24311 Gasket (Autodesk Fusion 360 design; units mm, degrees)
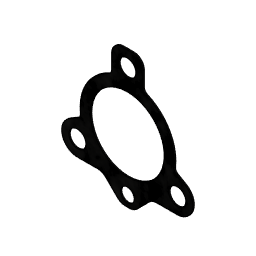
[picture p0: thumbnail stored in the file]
parameter "Bolt_Hole_Tolerance" = 0.7937 (= "( 1 / 32 ) * 1 in")
parameter "Bell_Tolerance" = 0.1984 (= "( 1 / 128 ) * 1 in")
parameter "Orifice_Hole_Tolerance" = 0.1984 (= "( 1 / 128 ) * 1 in")
parameter "d6" = 11.1125 (= "( 7 / 16 ) * 1 in")
sketch "Main Profile" plane through (0, 0, 0) normal (0, 1, 0) x axis (1, 0, 0)
  line L1 (0, -34.925) -> (0, 0)
  line L2 (0, -44.45) -> (0, -34.925)
  line L3 (3.175, -44.45) -> (-3.175, -44.45)
  line L4 (30.2459, 17.4625) -> (0, 0)
  line L5 (-30.2459, 17.4625) -> (0, 0)
  line L6 (9.525, -29.0994) -> (9.525, -38.1)
  line L7 (30.2459, 26.9875) -> (15.0812, 26.9875)
  line L8 (29.9633, 6.3008) -> (35.0084, 9.2136)
  line L9 (0, 31.75) -> (0, 0)
  line L10 (0, 38.1) -> (0, 31.75)
  line L11 (3.9688, 38.1) -> (-3.9688, 38.1)
  line L12 (15.0812, 26.9875) -> (3.9688, 38.1)
  line L13 (-15.0812, 26.9875) -> (-3.9688, 38.1)
  line L14 (-30.2459, 26.9875) -> (-15.0812, 26.9875)
  line L15 (-29.9633, 6.3008) -> (-35.0084, 9.2136)
  line L16 (-9.525, -29.0994) -> (-9.525, -38.1)
  circle C1 centre (0, 0) radius 22.3242
  circle C2 centre (0, -34.925) radius 5.1594
  circle C3 centre (30.2459, 17.4625) radius 5.1594
  circle C4 centre (-30.2459, 17.4625) radius 5.1594
  arc A1 centre (3.175, -38.1) radius 6.35 clockwise from (9.525, -38.1) to (3.175, -44.45)
  arc A2 centre (12.7, -29.0994) radius 3.175 clockwise from (9.525, -29.0994) to (11.43, -26.1894)
  arc A3 centre (0, 0) radius 28.575 clockwise from (28.3957, 3.196) to (11.43, -26.1894)
  arc A4 centre (30.2459, 17.4625) radius 9.525 clockwise from (30.2459, 26.9875) to (35.0084, 9.2136)
  arc A5 centre (31.5508, 3.5512) radius 3.175 clockwise from (28.3957, 3.196) to (29.9633, 6.3008)
  circle C5 centre (0, 31.75) radius 3.9688
  arc A6 centre (-30.2459, 17.4625) radius 9.525 clockwise from (-35.0084, 9.2136) to (-30.2459, 26.9875)
  arc A7 centre (-31.5508, 3.5512) radius 3.175 clockwise from (-29.9633, 6.3008) to (-28.3957, 3.196)
  arc A8 centre (0, 0) radius 28.575 clockwise from (-11.43, -26.1894) to (-28.3957, 3.196)
  arc A9 centre (-12.7, -29.0994) radius 3.175 clockwise from (-11.43, -26.1894) to (-9.525, -29.0994)
  arc A10 centre (-3.175, -38.1) radius 6.35 clockwise from (-3.175, -44.45) to (-9.525, -38.1)
  point P1 (0, 0)
  point P2 (0, 0)
  point P3 (0, 0)
  point P4 (0, -34.925)
  point P5 (0, -34.925)
  point P6 (0, -34.925)
  point P10 (0, -44.45)
  point P7 (0, -44.45)
  point P30 (0, 31.75)
  point P31 (0, 31.75)
  point P32 (0, 31.75)
  point P36 (0, 38.1)
  point P33 (0, 38.1)
  point P9 (3.175, -44.45)
  point P51 (-3.175, -44.45)
  point P17 (9.525, -38.1)
  point P49 (-9.525, -38.1)
  point P19 (9.525, -29.0994)
  point P48 (-9.525, -29.0994)
  point P20 (11.43, -26.1894)
  point P46 (-11.43, -26.1894)
  point P22 (28.3957, 3.196)
  point P44 (-28.3957, 3.196)
  point P24 (15.0812, 26.9875)
  point P38 (-15.0812, 26.9875)
  point P25 (30.2459, 26.9875)
  point P39 (-30.2459, 26.9875)
  point P26 (35.0084, 9.2136)
  point P41 (-35.0084, 9.2136)
  point P28 (29.9633, 6.3008)
  point P42 (-29.9633, 6.3008)
  point P35 (3.9688, 38.1)
  point P37 (-3.9688, 38.1)
  point P14 (0, 0)
  point P34 (-3.9688, 38.1)
  point P23 (0, 0)
  point P11 (0, 0)
  coincident P1 P2
  coincident P1 P3
  vertical L1
  coincident P4 P5
  coincident P5 P6
  vertical L2
  horizontal L3
  midpoint L3 P10
  coincident P7 P10
  tangent L3 A1
  vertical L6
  tangent A1 L6
  tangent L6 A2
  tangent A2 A3
  concentric C1 A3
  horizontal L7
  tangent L7 A4
  concentric C3 A4
  tangent A4 L8
  tangent L8 A5
  tangent A3 A5
  parallel L1 L9
  coincident P30 P31
  coincident P31 P32
  parallel L9 L10
  horizontal L11
  midpoint L11 P36
  coincident P33 P36
  symmetric L1 P9 P51
  symmetric L1 P17 P49
  symmetric L1 A1 A10
  symmetric L1 P19 P48
  symmetric L1 P20 P46
  symmetric L1 A2 A9
  symmetric L1 P22 P44
  symmetric L1 A3 A8
  symmetric L1 P24 P38
  symmetric L1 P25 P39
  symmetric L1 P26 P41
  symmetric L1 A4 A6
  symmetric L1 P28 P42
  symmetric L1 A5 A7
  symmetric L1 P35 P37
  dimension "d1" diameter C1 = 44.6484 (= "1 3/4  + Bell_Tolerance")
  dimension "d2" diameter C2 = 10.3188 (= "( 3 / 8 ) * 1 in + Bolt_Hole_Tolerance")
  dimension "d3" distance P3 P4 = 34.925 (= "1 3/8")
  dimension "d7" radius A1 = 6.35 (= "( 1 / 4 ) * 1 in")
  dimension "d8" distance P5 L6 = 9.525
  dimension "d9" radius A2 = 3.175 (= "( 1 / 8 ) * 1 in")
  dimension "d11" radius A4 = 9.525
  dimension "d12" angle L7 L8 = 30
  dimension "d13" radius A5 = 3.175 (= "( 1 / 8 ) * 1 in")
  dimension "d14" distance P14 P30 = 31.75 (= "1 1/4")
  dimension "d15" diameter C5 = 7.9375 (= "( 5 / 16 ) * 1 in")
  dimension "d16" distance P34 P35 = 7.9375 (= "( 5 / 16 ) * 1 in")
  dimension "d18" angle L7 L12 = 135
  dimension "d25" radius A3 = 28.575
  dimension "d26" distance L3 P23 = 44.45 (= "1 3/4")
  dimension "d27" distance P11 L11 = 38.1
  dimension "d5" C-Pattern1-Angle = 360
extrude "Extrude1" new body sketch "Main Profile" profile of C1 C2 L3 C3 C4 A1 L6 A2 A3 L7 A4 L8 A5 C5 L11 L12 L13 L14 A6 L15 A7 A8 A9 L16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 along normal blind 0.7937 (= "( 1 / 32 ) * 1 in") bodies "24311 Gasket"
fillet "Fillet1" radius 6.35 (= "( 1 / 4 ) * 1 in")
offset_faces "OffsetFaces1"
named bodies: "24311 Gasket"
